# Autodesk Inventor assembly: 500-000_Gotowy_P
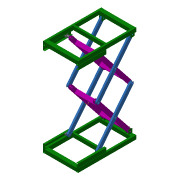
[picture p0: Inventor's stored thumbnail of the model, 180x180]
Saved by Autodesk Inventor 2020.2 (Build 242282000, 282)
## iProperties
Created: 2016-09
Part Number: 500-000_Gotowy_P
Document SubType Name: Assembly
Designer: F.Stasiak
Manager: www.cadconsulting.pl
Company: Fabian Stasiak CAD Consulting
Author: F.Stasiak
Subject: Zbiór ćwiczeń. Autodesk Inventor 2020. Kurs podstawowy
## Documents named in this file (7)
- C:\2020_Kurs_podstawowy\R6 Zespoły\Warsztat\Gotowe\500-000_Gotowy_P.iam
- C:\2020_Kurs_podstawowy\R6 Zespoły\Warsztat\Komponenty\500-05-01.ipt
- C:\2020_Kurs_podstawowy\R6 Zespoły\Warsztat\Komponenty\500-06-01.ipt
- C:\2020_Kurs_podstawowy\R6 Zespoły\Warsztat\Komponenty\500-001_Gotowy_P.iam
- C:\2020_Kurs_podstawowy\R6 Zespoły\Warsztat\Komponenty\500-002_Gotowy_P.iam
- C:\2020_Kurs_podstawowy\R6 Zespoły\Warsztat\Komponenty\500-003_Gotowy_P.iam
- C:\2020_Kurs_podstawowy\R6 Zespoły\Warsztat\Komponenty\500-004_Gotowy_P.iam
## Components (12 placed, 6 different names)
1. 500-001_Gotowy_P:1 [sub-assembly] — Obrotowe:1, przesuwne:3, PODNIESIENIE
2. 500-002_Gotowy_P:1 [sub-assembly] — Obrotowe:12, przesuwne:3, PODNIESIENIE
3. 500-003_Gotowy_P:1 [sub-assembly] — Obrotowe:2, Obrotowe:3, Obrotowe:8
4. 500-003_Gotowy_P:2 [sub-assembly] — Obrotowe:4, Obrotowe:5, Obrotowe:10
5. 500-003_Gotowy_P:3 [sub-assembly] — Obrotowe:6, Obrotowe:11, Obrotowe:12
6. 500-003_Gotowy_P:4 [sub-assembly] — Obrotowe:7, Obrotowe:9
7. 500-004_Gotowy_P:1 [sub-assembly] — Obrotowe:1, Obrotowe:2, Obrotowe:4, Obrotowe:6, Obrotowe:7
8. 500-004_Gotowy_P:2 [sub-assembly] — Obrotowe:8, Obrotowe:9, Obrotowe:10, Obrotowe:11, Obrotowe:13, Obrotowe:14
9. 500-05-01:1 — Obrotowe:3
10. 500-05-01:2 — Obrotowe:5
11. 500-06-01:1 — Obrotowe:14
12. 500-06-01:2 — Obrotowe:13
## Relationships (16: RevoluteJoint 14, TranslationJoint 2)
- Obrotowe:1 [RevoluteJoint]: 500-001_Gotowy_P:1 ↔ 500-004_Gotowy_P:1
- Obrotowe:2 [RevoluteJoint]: 500-003_Gotowy_P:1 ↔ 500-004_Gotowy_P:1
- Obrotowe:3 [RevoluteJoint]: 500-003_Gotowy_P:1 ↔ 500-05-01:1
- Obrotowe:4 [RevoluteJoint]: 500-003_Gotowy_P:2 ↔ 500-004_Gotowy_P:1
- Obrotowe:5 [RevoluteJoint]: 500-003_Gotowy_P:2 ↔ 500-05-01:2
- Obrotowe:6 [RevoluteJoint]: 500-003_Gotowy_P:3 ↔ 500-004_Gotowy_P:1
- Obrotowe:7 [RevoluteJoint]: 500-003_Gotowy_P:4 ↔ 500-004_Gotowy_P:1
- Obrotowe:8 [RevoluteJoint]: 500-003_Gotowy_P:1 ↔ 500-004_Gotowy_P:2
- Obrotowe:9 [RevoluteJoint]: 500-003_Gotowy_P:4 ↔ 500-004_Gotowy_P:2
- Obrotowe:10 [RevoluteJoint]: 500-003_Gotowy_P:2 ↔ 500-004_Gotowy_P:2
- Obrotowe:11 [RevoluteJoint]: 500-003_Gotowy_P:3 ↔ 500-004_Gotowy_P:2
- Obrotowe:12 [RevoluteJoint]: 500-002_Gotowy_P:1 ↔ 500-003_Gotowy_P:3
- Obrotowe:13 [RevoluteJoint]: 500-004_Gotowy_P:2 ↔ 500-06-01:2
- Obrotowe:14 [RevoluteJoint]: 500-004_Gotowy_P:2 ↔ 500-06-01:1
- przesuwne:3 [TranslationJoint]: 500-001_Gotowy_P:1 ↔ 500-002_Gotowy_P:1
- PODNIESIENIE [TranslationJoint]: 500-001_Gotowy_P:1 ↔ 500-002_Gotowy_P:1
